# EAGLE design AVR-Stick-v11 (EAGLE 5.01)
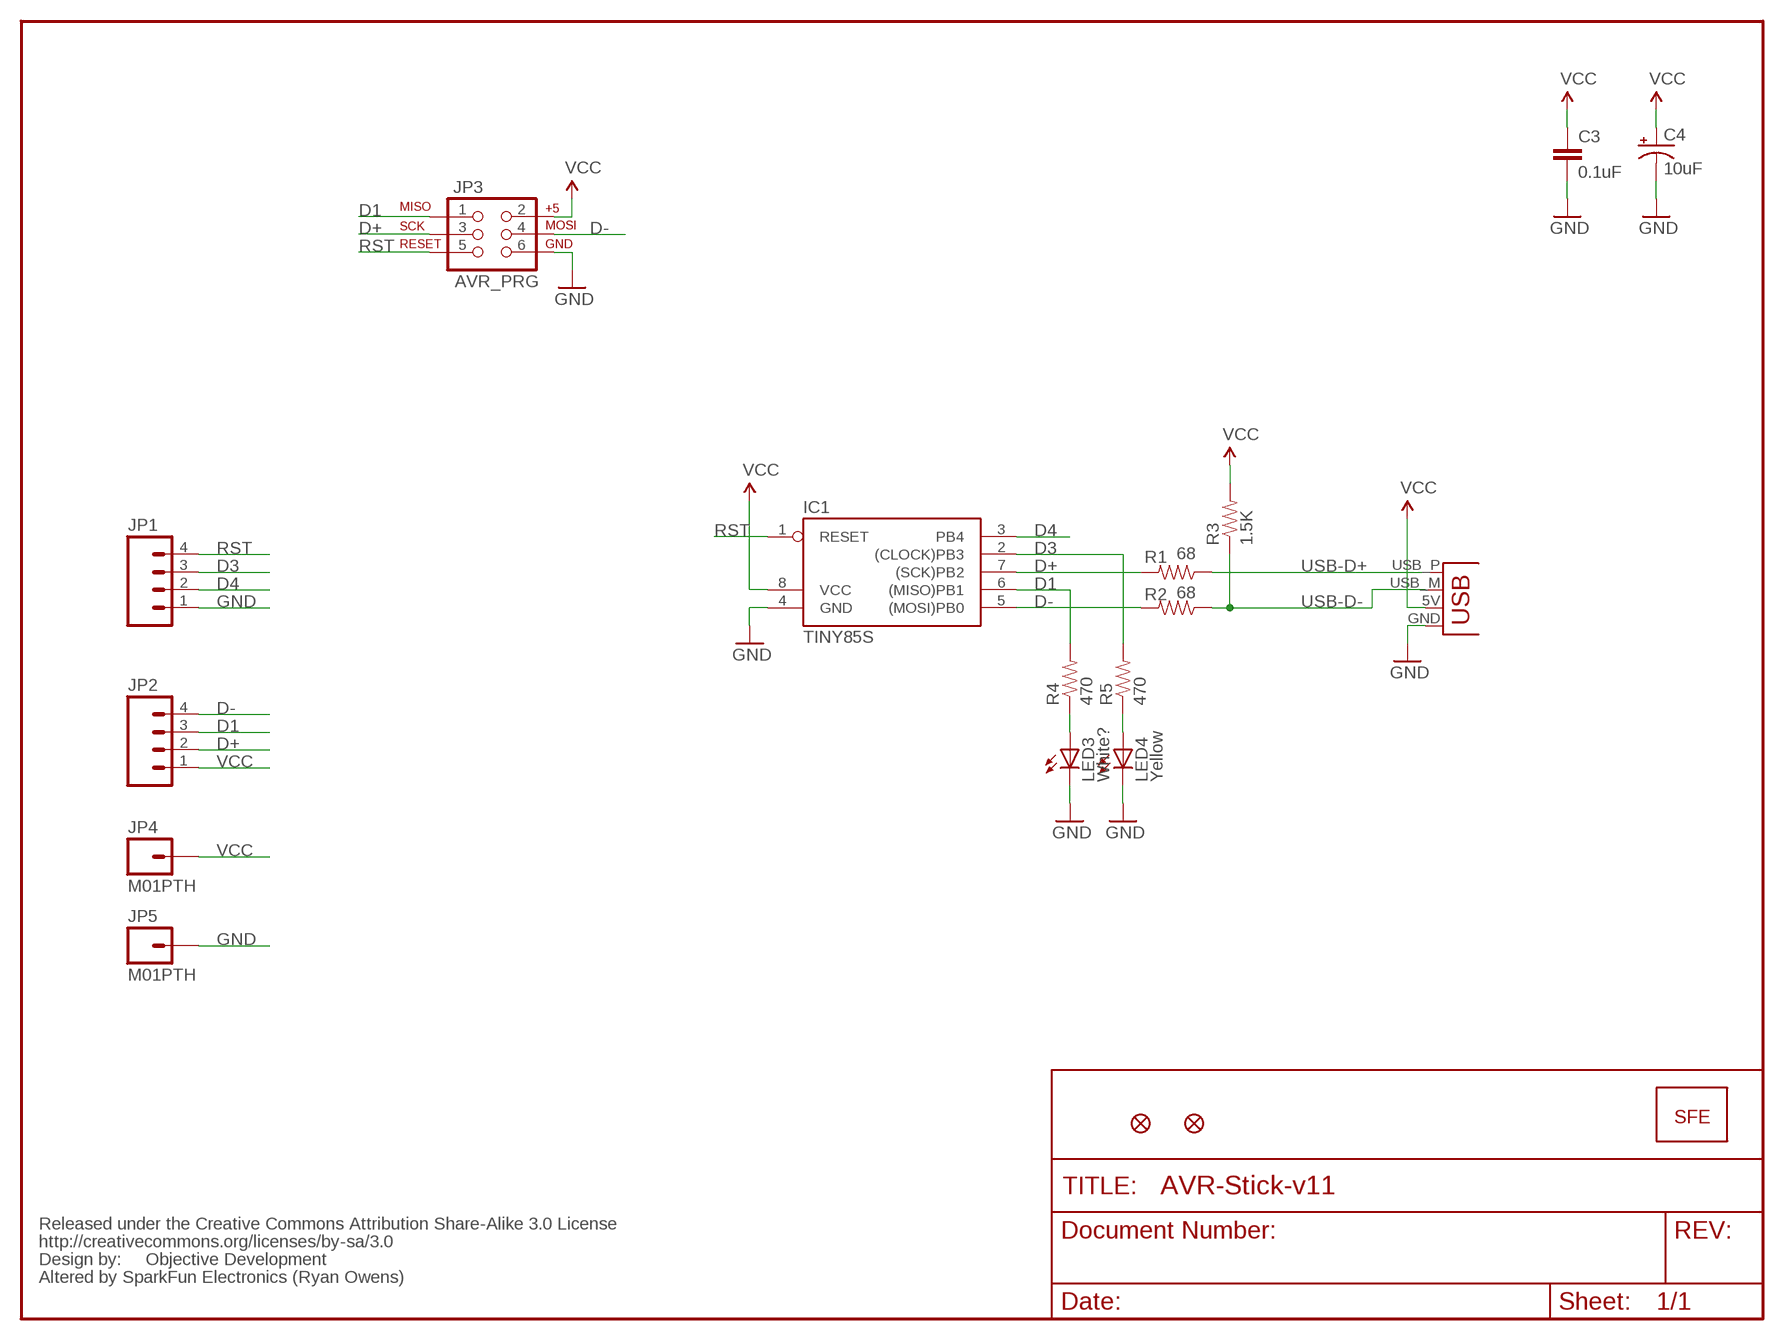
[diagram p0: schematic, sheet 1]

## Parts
C3  0.1uF  CAP0402  [C0402]
C4  10uF  CAP_POL1206  [EIA3216]
IC1  TINY85S  [SOIC8]
JP1  M04PTH  [1X04]
JP2  M04PTH  [1X04]
JP3  AVR_PRG  AVR_SPI_PRG_6PTH  [2X3]
JP4  M01PTH  [1X01]
JP5  M01PTH  [1X01]
LED3  White?  LED0603  [LED-0603]
LED4  Yellow  LED0603  [LED-0603]
R1  68  RESISTOR0402  [C0402]
R2  68  RESISTOR0402  [C0402]
R3  1.5K  RESISTOR0402  [C0402]
R4  470  RESISTOR0402  [C0402]
R5  470  RESISTOR0402  [C0402]
U$1  LOGO-SFESK  [SFE-LOGO-FLAME]
U$2  FIDUCIAL1X2  [FIDUCIAL-1X2]
U$3  FIDUCIAL1X2  [FIDUCIAL-1X2]
U$4  CREATIVE_COMMONS  [CREATIVE_COMMONS]
X1  USBPCB  [USB-A-PCB]

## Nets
D1: IC1.6((MISO)PB1) JP2.3 JP3.1 R4.2
D3: IC1.2((CLOCK)PB3) JP1.3 R5.2
D4: IC1.3(PB4) JP1.2
D+: IC1.7((SCK)PB2) JP2.2 JP3.3 R1.2
D-: IC1.5((MOSI)PB0) JP2.4 JP3.4 R2.2
GND: C3.2 C4.C(-) IC1.4(GND) JP1.1 JP3.6 JP5.1 LED3.C LED4.C X1.GND
N$7: LED3.A R4.1
N$9: LED4.A R5.1
RST: IC1.1(RESET) JP1.4 JP3.5
USB-D+: R1.1 X1.USB_P(D+)
USB-D-: R2.1 R3.1 X1.USB_M(D-)
VCC: C3.1 C4.A(+) IC1.8(VCC) JP2.1 JP3.2 JP4.1 R3.2 X1.5V(VBUS)

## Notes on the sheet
- Objective Development
- Altered by SparkFun Electronics (Ryan Owens)

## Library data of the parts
C3 = SparkFun:CAP: Capacitor
C4 = SparkFun:CAP_POL: Capacitor Polarized
IC1 = atmel:TINY85: MICROCONTROLLER 1K ROM 128 bytes RAM 128 bytes EEPROM
JP1 JP2 = SparkFun:M04: Header 4 Standard 4-pin 0.1" header. Use with straight break away headers (SKU : PRT-00116), right angle break away headers (PRT-00553), swiss pins (PRT-00743), machine pins (PRT-00117), and female headers (PRT-00115). Molex polarized connector foot print use with SKU : PRT-08231 with associated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
JP3 = SparkFun:AVR_SPI_PRG_6: AVR ISP 6 Pin This is the reduced ISP connector for AVR programming. Common on Arduino. This footprint will take up less PCB space and can be used with a 10-pin to 6-pin adapter such as SKU: BOB-08508
JP4 JP5 = SparkFun:M01: Header 1
LED3 LED4 = SparkFun:LED: LEDs
R1-R5 = SparkFun:RESISTOR: Resistor
U$1 = SparkFun:LOGO-SFE: Spark Fun Electronics PCB Logo
U$2 U$3 = SparkFun:FIDUCIAL: Fiducial Alignment Points
U$4 = SparkFun:CREATIVE_COMMONS
X1 = SparkFun:USB: USB Connectors USB-B-PTH is fully proven SKU : PRT-00139 USB-miniB is fully proven SKU : PRT-00587 USB-A-PCB is untested. USB-A-H is throughly reviewed, but untested. Spark Fun Electronics SKU : PRT-00437 USB-B-SMT is throughly reviewed, but untested. Needs silkscreen touching up. USB-A-S has not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

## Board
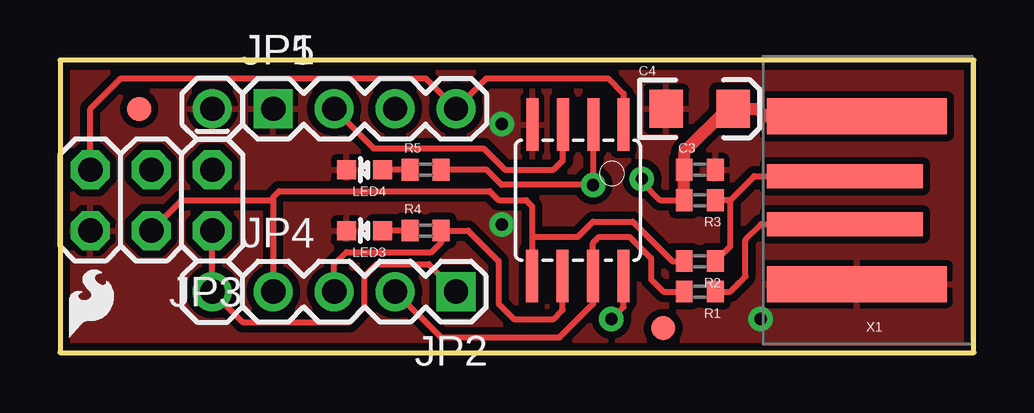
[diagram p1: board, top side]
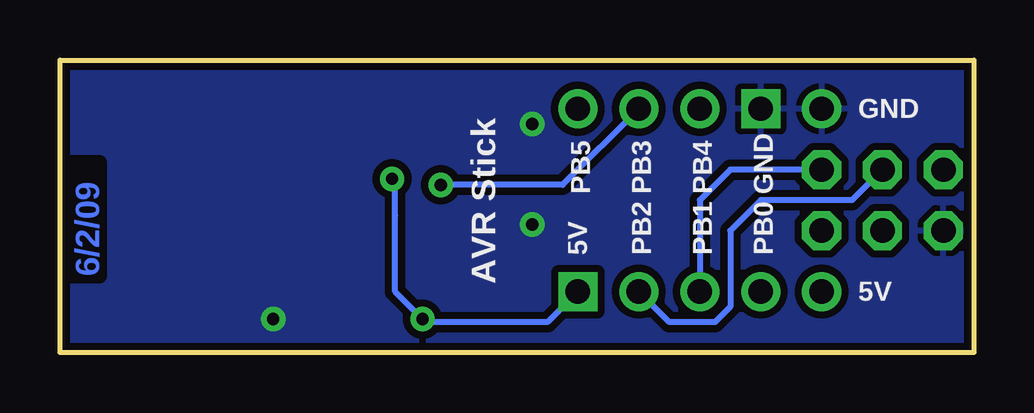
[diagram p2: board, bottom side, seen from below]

Size 38.1 x 12.19 mm. Coordinates in mm from the lower left corner, seen from the top.
Outline: 0,0 38.1,0 38.1,12.19 0,12.19 0,0
Copper layers (1*16): Top 0.035mm / dielectric 1.5mm / Bottom 0.035mm
Design rules "SparkFun": minimum track width 8mil, minimum drill 20mil, track to track 8mil, track to pad 8mil, pad to pad 8mil, via to via 8mil, smd to smd 8mil, copper to edge 10mil, drill to drill 8mil, minimum pad ring 12mil, minimum via ring 10mil, stop-mask expansion 4mil, vias tented up to drill 25mil, thermal gap 10mil

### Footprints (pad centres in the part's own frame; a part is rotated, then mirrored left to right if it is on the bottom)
C0402 = smd 0.7 x 0.9: 1 -0.65,0; 2 0.65,0
EIA3216 = smd 1.4 x 1.6: A 1.4,0; C -1.4,0
SOIC8 = smd 0.5 x 2.2: 1 -1.905,-3.154; 2 -0.645,-3.154; 3 0.625,-3.154; 4 1.895,-3.154; 5 1.905,3.154; 6 0.635,3.154; 7 -0.635,3.154; 8 -1.905,3.154
1X04 = drill 1.016 square: 1 0,0 | drill 1.016 round: 2 2.54,0; 3 5.08,0; 4 7.62,0
2X3 = drill 1.016 octagon: 1 0,0; 2 0,2.54; 3 2.54,0; 4 2.54,2.54; 5 5.08,0; 6 5.08,2.54
1X01 = drill 1.016 round: 1 0,0
LED-0603 = smd 0.8 x 0.8: A 0,-0.75; C 0,0.75
FIDUCIAL-1X2 = smd 1 x 1: 1 0,0
USB-A-PCB = smd 7.5 x 1.5: 5V -0.2,-3.5; GND -0.2,3.5 | smd 6.5 x 1: USB_M 0.3,-1; USB_P 0.3,1

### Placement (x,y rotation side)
C3  26.67,7.62 0 top
C4  26.67,10.16 0 top
IC1  21.59,6.35 180 top
JP1  8.89,10.16 0 top
JP2  16.51,2.54 180 top
JP3  6.35,7.62 180 top
JP4  6.35,2.54 0 top
JP5  6.35,10.16 0 top
LED3  12.7,5.08 90 top
LED4  12.7,7.62 90 top
R1  26.67,2.54 180 top
R2  26.67,3.81 180 top
R3  26.67,6.35 180 top
R4  15.24,5.08 0 top
R5  15.24,7.62 0 top
U$1  0.38,0.64 0 top
U$2  25.15,1.02 0 top
U$3  3.3,10.16 0 top
U$4  not placed on the board
X1  33.02,6.35 180 top

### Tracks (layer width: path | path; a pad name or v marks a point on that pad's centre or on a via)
D1
  Top 0.254: JP2.3 11.43,3.68 11.94,4.19 15.49,4.19 15.89,4.59 R4.2 17.02,5.08 18.29,3.81 18.29,2.03 18.92,1.4 20.57,1.4 20.95,1.78 IC1.6
  Bottom 0.254: JP3.1 10.16,7.62 11.43,6.35 JP2.3
D3  (via drill 0.51)
  Top 0.254: R5.2 17.78,7.62 18.41,6.99 v22.23,6.99 v22.23,7 IC1.2
  Bottom 0.254: JP1.3 17.14,6.99 v22.23,6.99
D4
  Top 0.254: IC1.3 20.96,8.01 20.57,7.62 18.54,7.62 17.65,8.51 13.08,8.51 12.95,8.64 JP1.2
D+
  Top 0.254: R1.2 25.15,2.54 24.64,3.05 24.64,3.94 23.75,4.83 22.48,4.83 22.23,4.57 IC1.7 22.23,2.03 20.83,0.64 15.88,0.64 JP2.2
  Bottom 0.254: JP3.3 5.08,6.35 8.89,6.35 10.16,5.08 10.16,1.91 10.79,1.27 12.7,1.27 JP2.2
D-
  Top 0.254: R2.2 25.53,3.81 23.88,5.46 22.23,5.46 21.59,4.83 19.68,4.83 | JP3.4 5.08,6.35 8.89,6.35 | 8.89,6.35 JP2.4 | 8.89,6.35 8.89,6.48 9.14,6.73 17.91,6.73 18.29,6.35 19.43,6.35 19.68,6.1 19.68,5.46 19.68,4.83 | 19.68,4.83 IC1.5
GND  (via drill 0.51)
  other vias: 18.41,9.53 18.41,5.33 29.21,1.4
  pour Bottom (isolate 0.305): 0,12.19 38.1,12.19 38.1,0 0,0
  pour Top (isolate 0.305): 0,0 0,12.19 38.1,12.19 38.1,0
N$7
  Top 0.254: R4.1 LED3.A
N$9
  Top 0.254: R5.1 LED4.A
RST
  Top 0.254: IC1.1 23.5,10.79 22.86,11.43 17.78,11.43 JP1.4 15.24,11.43 2.54,11.43 1.27,10.16 JP3.5
USB-D+
  Top 0.254: X1.USB_P 29.23,5.35 29.21,5.33 28.57,4.7 28.57,3.17 28.32,2.92 28.26,2.86 27.94,2.54 R1.1
USB-D-
  Top 0.254: X1.USB_M 28.94,7.35 27.94,6.35 | 27.94,6.35 R3.1 | 27.94,6.35 27.94,5.2 27.94,5.08 27.94,4.43 R2.1
VCC  (via drill 0.51)
  Top 0.254: IC1.8 23.5,1.91 v22.99,1.4 | JP2.1 15.37,3.68 13.21,3.68 12.7,3.17 12.7,1.91 12.06,1.27 7.62,1.27 JP4.1 JP3.2 | R3.2 25.02,6.35 24.26,7.11 v24.26,7.24
  Top 0.508: X1.5V 29.39,9.85 29.08,10.16 C4.A 27.81,10.16 26.04,8.38 26.04,7.63 C3.1 R3.2
  Bottom 0.254: JP2.1 17.78,1.27 22.86,1.27 v22.99,1.4 24.13,2.54 24.13,5.71 24.13,7.11 v24.26,7.24

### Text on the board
Bottom: 6/2/09
bPlace: GND | AVR Stick | GND | PB4 | PB3 | PB5 | PB0 | PB1 | PB2 | 5V | 5V
tValues: Objective Development | Altered by SparkFun Electronics (Ryan Owens)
